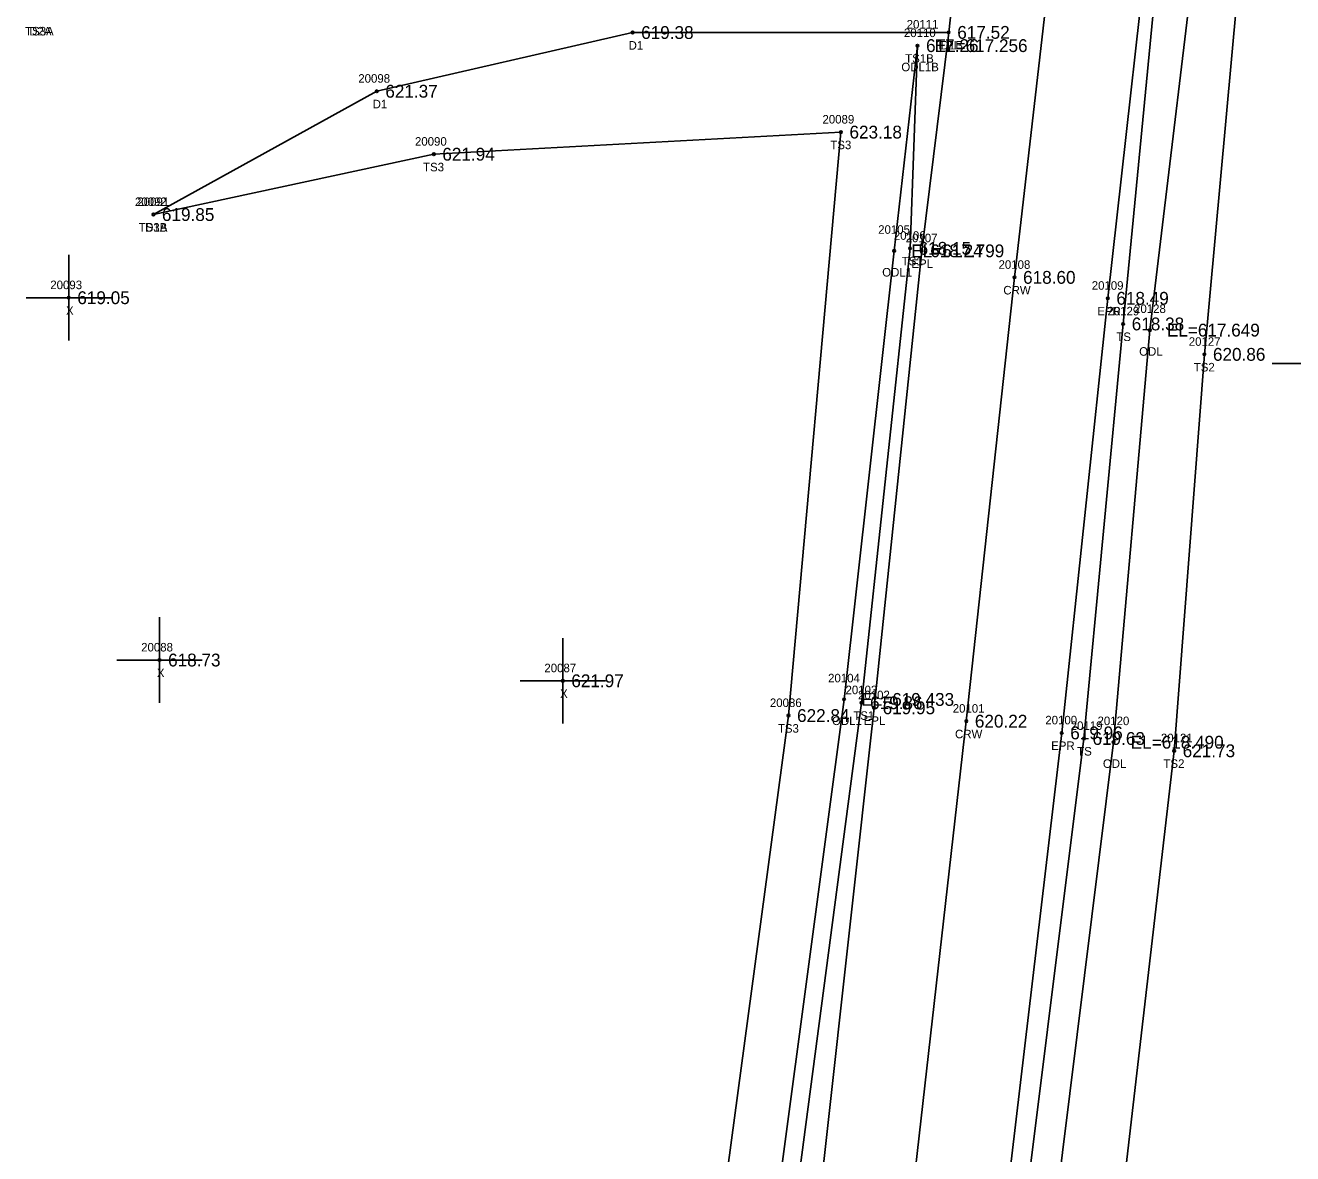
# Model space of a CAD drawing. Extents: x 1695443 to 1696344, y 1087542 to 1090645.
# Drawn here: x 1695809.6 to 1695957.9, y 1087923.6 to 1088055.6 of the extents above; entities that cross this region are included whole.
import ezdxf

# ---------------------------------------------------------------- set-up
doc = ezdxf.new("R2010")
doc.units = 0
for name, color, linetype in [('RD_DTM_BkLn1', 7, 'Continuous'), ('RD_DTM_BkLn2', 7, 'Continuous'), ('RD_DTM_BkLn_txCode', 7, 'Continuous'), ('RD_EX_Driveway', 7, 'Continuous'), ('RD_EX_Driveway_txCode', 7, 'Continuous'), ('RD_EX_H2O', 7, 'Continuous'), ('RD_EX_H2O_txCode', 7, 'Continuous'), ('RD_EX_Misc', 7, 'Continuous'), ('RD_EX_Misc_txCode', 7, 'Continuous'), ('RD_EX_Road', 7, 'Continuous'), ('RD_EX_Road_txCode', 7, 'Continuous'), ('RD_EX_TX_Driveway_ELEV', 7, 'Continuous'), ('RD_EX_TX_H2O_ELEV', 7, 'Continuous'), ('RD_EX_TX_Misc_ELEV', 7, 'Continuous'), ('RD_EX_TX_Road_ELEV', 7, 'Continuous'), ('RD_HC_Survey_ELEV', 7, 'Continuous'), ('RD_HC_Survey_txCode', 7, 'Continuous'), ('RD_SMD_Locator', 7, 'Continuous')]:
    doc.layers.add(name, color=color, linetype=linetype)

msp = doc.modelspace()

# ---------------------------------------------------------------- linework, layer by layer
at = {"layer": 'RD_DTM_BkLn1'}
msp.add_lwpolyline([(1695869.23, 1087563.38), (1695882.71, 1087666.87), (1695895.39, 1087768.85), (1695908.05, 1087871.3), (1695919.71, 1087974.19), (1695925.35, 1088026.13), (1695931.27, 1088077.73), (1695937.88, 1088128.75), (1695945.4, 1088182.97), (1695952.48, 1088232.38), (1695961.74, 1088286.36), (1695971.36, 1088336.92), (1695982.91, 1088390.82), (1696009.16, 1088497.22), (1696035.45, 1088601.7), (1696045.5, 1088655.66), (1696049.03, 1088705.78), (1696045.47, 1088756.42), (1696033.82, 1088809.1), (1696016.78, 1088855.71), (1695990.89, 1088906.17), (1695964.41, 1088947.39), (1695931.21, 1088992.88)], dxfattribs=at)
at = {"layer": 'RD_DTM_BkLn2'}
for points in [[(1695882.6, 1087560.4), (1695895.55, 1087664.54), (1695908.06, 1087766.74), (1695920.67, 1087869.68), (1695933.47, 1087972.17), (1695938.06, 1088020.68), (1695943.39, 1088076.15), (1695950.93, 1088126.12), (1695958.62, 1088180.79), (1695967.59, 1088232.03), (1695975.32, 1088283.22), (1695985.14, 1088336.17), (1695996.59, 1088387.88), (1696023.18, 1088492.82), (1696049.23, 1088599.85), (1696058.32, 1088654.25)], [(1695882.6, 1087560.4), (1695883.79, 1087555.85), (1695890.5, 1087560.67), (1695906.06, 1087668.38), (1695920.19, 1087765.58), (1695932.4, 1087870.37), (1695944.02, 1087970.73), (1695947.56, 1088017.12), (1695952.59, 1088072.2), (1695957.06, 1088113.91)], [(1695882.18, 1087796.26), (1695885.89, 1087802.68), (1695893.96, 1087874.12), (1695907.45, 1087976.35), (1695913.13, 1088029.53), (1695914, 1088053.25)], [(1695882.18, 1087796.26), (1695877.51, 1087802.83), (1695885.49, 1087874.87), (1695898.91, 1087974.85), (1695905.04, 1088043.13), (1695857.41, 1088040.54), (1695824.61, 1088033.48)]]:
    msp.add_lwpolyline(points, dxfattribs=at)
at = {"layer": 'RD_EX_Driveway'}
msp.add_lwpolyline([(1695824.61, 1088033.48), (1695850.74, 1088047.91), (1695880.67, 1088054.78), (1695917.65, 1088054.8)], dxfattribs=at)
at = {"layer": 'RD_EX_H2O'}
for points in [[(1695884.7, 1087558.83), (1695897.39, 1087664.39), (1695910.4, 1087766.5), (1695924.17, 1087869.12), (1695936.94, 1087971.73), (1695941.17, 1088019.96), (1695947.61, 1088073.49), (1695957.06, 1088113.91)], [(1695882.18, 1087796.26), (1695891.76, 1087874.47), (1695905.41, 1087976.74), (1695911.27, 1088029.23), (1695914, 1088053.25)]]:
    msp.add_lwpolyline(points, dxfattribs=at)
at = {"layer": 'RD_EX_Misc'}
for p, q in [((1695814.71, 1088018.75), (1695814.71, 1088028.75)), ((1695809.71, 1088023.75), (1695819.71, 1088023.75)), ((1695955.5, 1088016.06), (1695965.5, 1088016.06)), ((1695825.33, 1087976.35), (1695825.33, 1087986.35)), ((1695872.5, 1087973.92), (1695872.5, 1087983.92)), ((1695820.33, 1087981.35), (1695830.33, 1087981.35)), ((1695867.5, 1087978.92), (1695877.5, 1087978.92))]:
    msp.add_line(p, q, dxfattribs=at)
at = {"layer": 'RD_EX_Road'}
for points in [[(1695879.87, 1087561.29), (1695893.33, 1087665.71), (1695905.96, 1087767.16), (1695918.66, 1087869.54), (1695930.87, 1087972.82), (1695936.26, 1088023.68), (1695942.14, 1088076.32), (1695948.07, 1088128.17), (1695955.04, 1088181.4), (1695962.88, 1088230.72), (1695971.68, 1088284.64), (1695982.02, 1088336.12), (1695993.28, 1088388.48), (1696018.75, 1088494.48), (1696045.23, 1088599.95), (1696055.72, 1088654.41), (1696060.15, 1088705.35), (1696055.83, 1088758.02), (1696044.01, 1088812.16), (1696026.4, 1088860.33), (1696000.41, 1088911.48), (1695972.46, 1088953.82), (1695939.48, 1088998.73), (1695931.21, 1088992.88)], [(1695858.19, 1087564.9), (1695871.71, 1087668.82), (1695884.5, 1087774.69), (1695887.48, 1087794.2), (1695897.57, 1087873.43), (1695908.92, 1087975.76), (1695914.49, 1088029.24), (1695917.65, 1088054.8), (1695920.27, 1088079.09), (1695926.98, 1088130.26), (1695934.75, 1088185.09), (1695942.15, 1088234.62), (1695951.36, 1088288.06), (1695961.48, 1088338.41), (1695972.86, 1088394.13), (1695998.53, 1088499.67), (1696024.81, 1088603.86), (1696034.83, 1088656.78)]]:
    msp.add_lwpolyline(points, dxfattribs=at)
at = {"layer": 'RD_SMD_Locator'}
for centre in [(1695880.67, 1088054.78), (1695917.65, 1088054.8), (1695917.65, 1088054.8), (1695914, 1088053.25), (1695914, 1088053.25), (1695850.74, 1088047.91), (1695905.04, 1088043.13), (1695857.41, 1088040.54), (1695824.61, 1088033.48), (1695824.61, 1088033.48), (1695911.27, 1088029.23), (1695913.13, 1088029.53), (1695914.49, 1088029.24), (1695925.35, 1088026.13), (1695814.71, 1088023.75), (1695936.26, 1088023.68), (1695938.06, 1088020.68), (1695941.17, 1088019.96), (1695947.56, 1088017.12), (1695825.33, 1087981.35), (1695872.5, 1087978.92), (1695905.41, 1087976.74), (1695907.45, 1087976.35), (1695898.91, 1087974.85), (1695908.92, 1087975.76), (1695919.71, 1087974.19), (1695930.87, 1087972.82), (1695933.47, 1087972.17), (1695936.94, 1087971.73), (1695944.02, 1087970.73)]:
    msp.add_circle(centre, 0.15, dxfattribs=at)

# ---------------------------------------------------------------- texts
at = {"layer": 'RD_DTM_BkLn_txCode'}
for s, p in [('TS3A', (1695809.6, 1088054.44)), ('20110', (1695912.41, 1088054.25)), ('TS1B', (1695912.56, 1088051.25)), ('20089', (1695902.88, 1088044.13)), ('20090', (1695855.21, 1088041.54)), ('TS3', (1695903.8, 1088041.13)), ('TS3', (1695856.16, 1088038.54)), ('20091', (1695822.74, 1088034.48)), ('TS3B', (1695822.89, 1088031.48)), ('20106', (1695911.23, 1088030.53)), ('TS1', (1695912.16, 1088027.53)), ('20129', (1695936.22, 1088021.68)), ('TS', (1695937.26, 1088018.68)), ('20127', (1695945.73, 1088018.12)), ('TS2', (1695946.32, 1088015.12)), ('20103', (1695905.58, 1087977.35)), ('20086', (1695896.73, 1087975.85)), ('TS1', (1695906.49, 1087974.35)), ('TS3', (1695897.67, 1087972.85)), ('20119', (1695931.92, 1087973.17)), ('20121', (1695942.47, 1087971.73)), ('TS', (1695932.68, 1087970.17)), ('TS2', (1695942.77, 1087968.73))]:
    msp.add_text(s, height=1, dxfattribs=at).set_placement(p)
at = {"layer": 'RD_EX_Driveway_txCode'}
for s, p in [('D2A', (1695810.09, 1088054.44)), ('D1', (1695880.2, 1088052.78)), ('D1B', (1695916.71, 1088052.8)), ('20098', (1695848.58, 1088048.91)), ('D1', (1695850.26, 1088045.91)), ('20092', (1695822.45, 1088034.48)), ('D1A', (1695823.65, 1088031.48))]:
    msp.add_text(s, height=1, dxfattribs=at).set_placement(p)
at = {"layer": 'RD_EX_H2O_txCode'}
for s, p in [('20111', (1695912.73, 1088055.25)), ('ODL1B', (1695912.11, 1088050.25)), ('20105', (1695909.4, 1088031.23)), ('ODL1', (1695909.87, 1088026.23)), ('20128', (1695939.33, 1088021.96)), ('ODL', (1695939.93, 1088016.96)), ('20104', (1695903.54, 1087978.74)), ('ODL1', (1695904, 1087973.74)), ('20120', (1695935.06, 1087973.73)), ('ODL', (1695935.69, 1087968.73))]:
    msp.add_text(s, height=1, dxfattribs=at).set_placement(p)
at = {"layer": 'RD_EX_Misc_txCode'}
for s, p in [('20093', (1695812.55, 1088024.75)), ('X', (1695814.39, 1088021.75)), ('20088', (1695823.18, 1087982.35)), ('20087', (1695870.35, 1087979.92)), ('X', (1695825.02, 1087979.35)), ('X', (1695872.19, 1087976.92))]:
    msp.add_text(s, height=1, dxfattribs=at).set_placement(p)
at = {"layer": 'RD_EX_Road_txCode'}
for s, p in [('EPL', (1695916.45, 1088052.8)), ('20107', (1695912.62, 1088030.24)), ('EPL', (1695913.29, 1088027.24)), ('20109', (1695934.38, 1088024.68)), ('EPR', (1695935.03, 1088021.68)), ('20102', (1695907.04, 1087976.76)), ('EPL', (1695907.71, 1087973.76)), ('20100', (1695928.95, 1087973.82)), ('EPR', (1695929.64, 1087970.82))]:
    msp.add_text(s, height=1, dxfattribs=at).set_placement(p)
at = {"layer": 'RD_EX_TX_Driveway_ELEV'}
for s, p in [('619.38', (1695881.67, 1088054.03)), ('617.52', (1695918.65, 1088054.05)), ('621.37', (1695851.74, 1088047.16)), ('619.85', (1695825.61, 1088032.73))]:
    msp.add_text(s, height=1.5, dxfattribs=at).set_placement(p)
at = {"layer": 'RD_EX_TX_H2O_ELEV'}
for s, p in [('EL=617.256', (1695916, 1088052.5)), ('EL=617.799', (1695913.27, 1088028.48)), ('EL=617.649', (1695943.17, 1088019.21)), ('EL=619.433', (1695907.41, 1087975.99)), ('EL=618.490', (1695938.94, 1087970.98))]:
    msp.add_text(s, height=1.5, dxfattribs=at).set_placement(p)
at = {"layer": 'RD_EX_TX_Misc_ELEV'}
for s, p in [('617.26', (1695915, 1088052.5)), ('623.18', (1695906.04, 1088042.38)), ('621.94', (1695858.41, 1088039.79)), ('619.85', (1695825.61, 1088032.73)), ('618.15', (1695914.13, 1088028.78)), ('619.05', (1695815.71, 1088023)), ('618.38', (1695939.06, 1088019.93)), ('620.86', (1695948.56, 1088016.37)), ('618.73', (1695826.33, 1087980.6)), ('621.97', (1695873.5, 1087978.17)), ('619.86', (1695908.45, 1087975.6)), ('622.84', (1695899.91, 1087974.1)), ('619.63', (1695934.47, 1087971.42)), ('621.73', (1695945.02, 1087969.98))]:
    msp.add_text(s, height=1.5, dxfattribs=at).set_placement(p)
at = {"layer": 'RD_EX_TX_Road_ELEV'}
for s, p in [('617.52', (1695918.65, 1088054.05)), ('618.24', (1695915.49, 1088028.49)), ('618.49', (1695937.26, 1088022.93)), ('619.95', (1695909.92, 1087975.01)), ('619.96', (1695931.87, 1087972.07))]:
    msp.add_text(s, height=1.5, dxfattribs=at).set_placement(p)
at = {"layer": 'RD_HC_Survey_ELEV'}
for s, p in [('618.60', (1695926.35, 1088025.38)), ('620.22', (1695920.71, 1087973.44))]:
    msp.add_text(s, height=1.5, dxfattribs=at).set_placement(p)
at = {"layer": 'RD_HC_Survey_txCode'}
for s, p in [('20108', (1695923.48, 1088027.13)), ('CRW', (1695924.04, 1088024.13)), ('20101', (1695918.12, 1087975.19)), ('CRW', (1695918.39, 1087972.19))]:
    msp.add_text(s, height=1, dxfattribs=at).set_placement(p)

doc.saveas('drawing.dxf')
